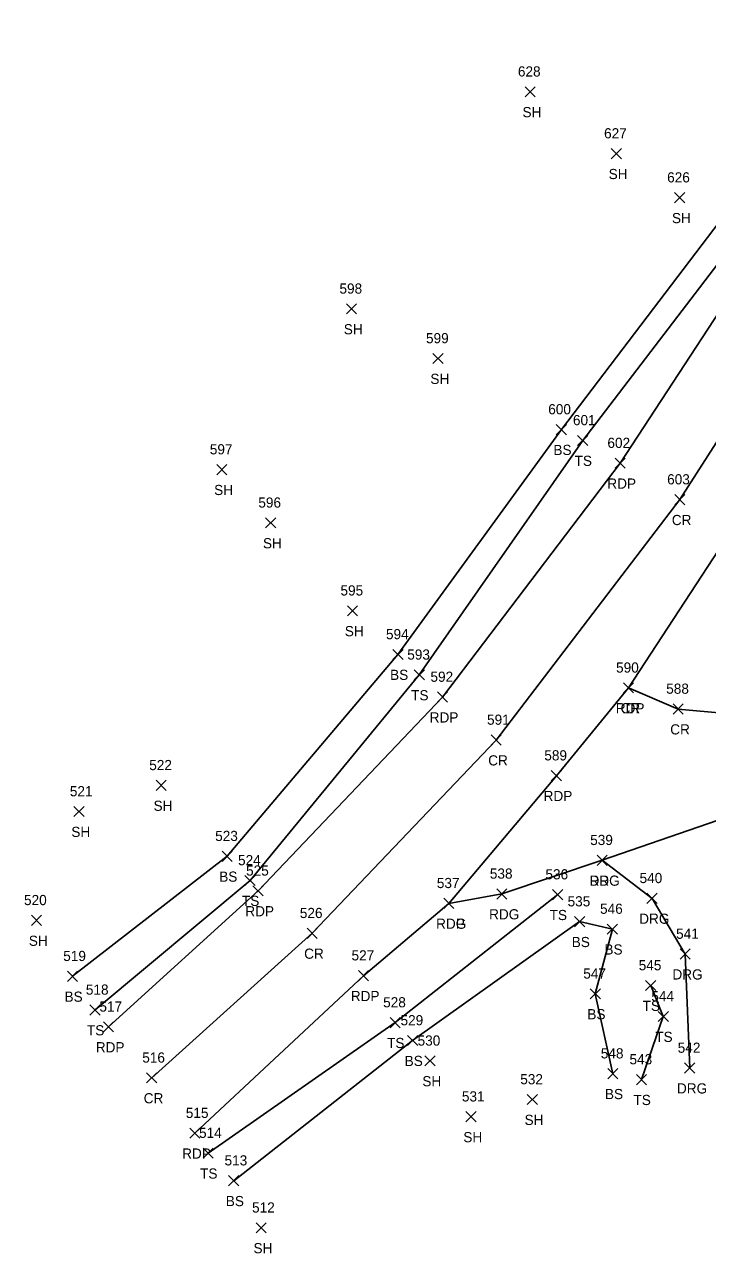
# Model space of a CAD drawing. Extents: x 1586965 to 1590952, y 716317 to 720029.
# Drawn here: x 1586964.8 to 1587099.1, y 719146.9 to 719388.4 of the extents above; entities that cross this region are included whole.
import ezdxf

# ---------------------------------------------------------------- set-up
doc = ezdxf.new("R2010")
doc.units = 0
for name, color, linetype in [('L_A', 7, 'Continuous'), ('L_I', 7, 'Continuous'), ('L_TIC', 7, 'Continuous'), ('LELB', 7, 'Continuous'), ('P_A', 7, 'Continuous'), ('P_I', 7, 'Continuous'), ('P_TIC', 7, 'Continuous'), ('PET', 7, 'Continuous'), ('PEU', 7, 'Continuous'), ('PRC', 7, 'Continuous'), ('R_A', 7, 'Continuous'), ('R_I', 7, 'Continuous'), ('R_TIC', 7, 'Continuous'), ('RDG', 7, 'Continuous')]:
    doc.layers.add(name, color=color, linetype=linetype)

msp = doc.modelspace()

# ---------------------------------------------------------------- linework, layer by layer
at = {"layer": 'L_TIC'}
for points in [[(1587063.22, 719374.22), (1587065.22, 719376.22)], [(1587065.22, 719374.22), (1587063.22, 719376.22)], [(1587080.16, 719362.06), (1587082.16, 719364.06)], [(1587082.16, 719362.06), (1587080.16, 719364.06)], [(1587092.61, 719353.4), (1587094.61, 719355.4)], [(1587094.61, 719353.4), (1587092.61, 719355.4)], [(1587028.08, 719331.55), (1587030.08, 719333.55)], [(1587030.08, 719331.55), (1587028.08, 719333.55)], [(1587045.11, 719321.8), (1587047.11, 719323.8)], [(1587047.11, 719321.8), (1587045.11, 719323.8)], [(1587069.35, 719307.83), (1587071.35, 719309.83)], [(1587071.35, 719307.83), (1587069.35, 719309.83)], [(1587073.55, 719305.69), (1587075.55, 719307.69)], [(1587075.55, 719305.69), (1587073.55, 719307.69)], [(1587002.59, 719299.96), (1587004.59, 719301.96)], [(1587004.59, 719299.96), (1587002.59, 719301.96)], [(1587012.19, 719289.49), (1587014.19, 719291.49)], [(1587014.19, 719289.49), (1587012.19, 719291.49)], [(1587028.28, 719272.22), (1587030.28, 719274.22)], [(1587030.28, 719272.22), (1587028.28, 719274.22)], [(1587037.23, 719263.63), (1587039.23, 719265.63)], [(1587039.23, 719263.63), (1587037.23, 719265.63)], [(1587041.41, 719259.62), (1587043.41, 719261.62)], [(1587043.41, 719259.62), (1587041.41, 719261.62)], [(1586990.68, 719237.9), (1586992.68, 719239.9)], [(1586992.68, 719237.9), (1586990.68, 719239.9)], [(1586974.51, 719232.76), (1586976.51, 719234.76)], [(1586976.51, 719232.76), (1586974.51, 719234.76)], [(1587003.64, 719223.97), (1587005.64, 719225.97)], [(1587005.64, 719223.97), (1587003.64, 719225.97)], [(1587008.14, 719219.21), (1587010.14, 719221.21)], [(1587010.14, 719219.21), (1587008.14, 719221.21)], [(1587068.64, 719216.43), (1587070.64, 719218.43)], [(1587070.64, 719216.43), (1587068.64, 719218.43)], [(1586966.15, 719211.37), (1586968.15, 719213.37)], [(1586968.15, 719211.37), (1586966.15, 719213.37)], [(1587072.95, 719211.12), (1587074.95, 719213.12)], [(1587074.95, 719211.12), (1587072.95, 719213.12)], [(1587079.38, 719209.66), (1587081.38, 719211.66)], [(1587081.38, 719209.66), (1587079.38, 719211.66)], [(1586973.22, 719200.38), (1586975.22, 719202.38)], [(1586975.22, 719200.38), (1586973.22, 719202.38)], [(1587086.92, 719198.57), (1587088.92, 719200.57)], [(1587088.92, 719198.57), (1587086.92, 719200.57)], [(1587076.02, 719196.93), (1587078.02, 719198.93)], [(1587078.02, 719196.93), (1587076.02, 719198.93)], [(1586977.66, 719193.77), (1586979.66, 719195.77)], [(1586979.66, 719193.77), (1586977.66, 719195.77)], [(1587036.67, 719191.28), (1587038.67, 719193.28)], [(1587038.67, 719191.28), (1587036.67, 719193.28)], [(1587089.4, 719192.48), (1587091.4, 719194.48)], [(1587091.4, 719192.48), (1587089.4, 719194.48)], [(1587040.1, 719187.75), (1587042.1, 719189.75)], [(1587042.1, 719187.75), (1587040.1, 719189.75)], [(1587043.54, 719183.76), (1587045.54, 719185.76)], [(1587045.54, 719183.76), (1587043.54, 719185.76)], [(1587079.48, 719181.24), (1587081.48, 719183.24)], [(1587081.48, 719181.24), (1587079.48, 719183.24)], [(1587085.12, 719180.08), (1587087.12, 719182.08)], [(1587087.12, 719180.08), (1587085.12, 719182.08)], [(1587063.63, 719176.16), (1587065.63, 719178.16)], [(1587065.63, 719176.16), (1587063.63, 719178.16)], [(1587051.59, 719172.78), (1587053.59, 719174.78)], [(1587053.59, 719172.78), (1587051.59, 719174.78)], [(1586999.91, 719165.62), (1587001.91, 719167.62)], [(1587001.91, 719165.62), (1586999.91, 719167.62)], [(1587004.93, 719160.21), (1587006.93, 719162.21)], [(1587006.93, 719160.21), (1587004.93, 719162.21)], [(1587010.33, 719150.95), (1587012.33, 719152.95)], [(1587012.33, 719150.95), (1587010.33, 719152.95)]]:
    msp.add_lwpolyline(points, dxfattribs=at)
at = {"layer": 'LELB'}
for points in [[(1586974.22, 719201.38), (1587004.64, 719224.97), (1587038.23, 719264.63), (1587070.35, 719308.83), (1587101.6, 719349.88), (1587119.36, 719390.75), (1587135.94, 719419.64), (1587149.18, 719457.32), (1587161.88, 719497.01), (1587171.82, 719537.32), (1587183.93, 719559.95), (1587196.31, 719595.67), (1587210.79, 719616.33), (1587226.54, 719644.19), (1587252.78, 719668.03), (1587275.41, 719699.75), (1587291.25, 719715.32), (1587307.92, 719729.13), (1587319.25, 719735.05), (1587320, 719753.34), (1587323.07, 719768.88), (1587320.57, 719781.92), (1587330.74, 719804.48), (1587340.87, 719823.38)], [(1586974.22, 719201.38), (1587004.64, 719224.97), (1587038.23, 719264.63), (1587070.35, 719308.83), (1587101.6, 719349.88), (1587119.36, 719390.75), (1587135.94, 719419.64), (1587149.18, 719457.32), (1587161.88, 719497.01), (1587171.82, 719537.32), (1587183.93, 719559.95), (1587196.31, 719595.67), (1587210.79, 719616.33), (1587226.54, 719644.19), (1587252.78, 719668.03), (1587275.41, 719699.75), (1587291.25, 719715.32), (1587307.92, 719729.13), (1587319.25, 719735.05), (1587320, 719753.34), (1587323.07, 719768.88), (1587320.57, 719781.92), (1587330.74, 719804.48), (1587340.87, 719823.38)], [(1586978.66, 719194.77), (1587009.14, 719220.21), (1587042.41, 719260.62), (1587074.55, 719306.69), (1587105.59, 719347.25), (1587126.81, 719387.29), (1587140.39, 719417.03), (1587155.04, 719455.09), (1587167.34, 719494.49), (1587179.82, 719533.81), (1587190.9, 719559.88), (1587204.29, 719592.61), (1587216.76, 719611.7), (1587236.63, 719636.62), (1587258.85, 719661.96), (1587283.81, 719691.81), (1587311.82, 719715.76), (1587323.53, 719725.34), (1587349.89, 719742.95), (1587377.37, 719757.84), (1587414.05, 719779.22)], [(1586978.66, 719194.77), (1587009.14, 719220.21), (1587042.41, 719260.62), (1587074.55, 719306.69), (1587105.59, 719347.25), (1587126.81, 719387.29), (1587140.39, 719417.03), (1587155.04, 719455.09), (1587167.34, 719494.49), (1587179.82, 719533.81), (1587190.9, 719559.88), (1587204.29, 719592.61), (1587216.76, 719611.7), (1587236.63, 719636.62), (1587258.85, 719661.96), (1587283.81, 719691.81), (1587311.82, 719715.76), (1587323.53, 719725.34), (1587349.89, 719742.95), (1587377.37, 719757.84), (1587414.05, 719779.22)], [(1587000.91, 719166.62), (1587037.67, 719192.28), (1587069.64, 719217.43)], [(1587000.91, 719166.62), (1587037.67, 719192.28), (1587069.64, 719217.43)], [(1587005.93, 719161.21), (1587041.1, 719188.75), (1587073.95, 719212.12), (1587080.38, 719210.66), (1587077.02, 719197.93), (1587080.48, 719182.24)], [(1587005.93, 719161.21), (1587041.1, 719188.75), (1587073.95, 719212.12), (1587080.38, 719210.66), (1587077.02, 719197.93), (1587080.48, 719182.24)], [(1587086.12, 719181.08), (1587090.4, 719193.48), (1587087.92, 719199.57)], [(1587086.12, 719181.08), (1587090.4, 719193.48), (1587087.92, 719199.57)]]:
    msp.add_lwpolyline(points, dxfattribs=at)
at = {"layer": 'P_TIC'}
for points in [[(1587080.9, 719301.22), (1587082.9, 719303.22)], [(1587082.9, 719301.22), (1587080.9, 719303.22)], [(1587092.64, 719294.06), (1587094.64, 719296.06)], [(1587094.64, 719294.06), (1587092.64, 719296.06)], [(1587082.56, 719257.07), (1587084.56, 719259.07)], [(1587084.56, 719257.07), (1587082.56, 719259.07)], [(1587082.56, 719257.07), (1587084.56, 719259.07)], [(1587084.56, 719257.07), (1587082.56, 719259.07)], [(1587045.97, 719255.26), (1587047.97, 719257.26)], [(1587047.97, 719255.26), (1587045.97, 719257.26)], [(1587092.33, 719252.91), (1587094.33, 719254.91)], [(1587094.33, 719252.91), (1587092.33, 719254.91)], [(1587056.54, 719246.82), (1587058.54, 719248.82)], [(1587058.54, 719246.82), (1587056.54, 719248.82)], [(1587068.37, 719239.81), (1587070.37, 719241.81)], [(1587070.37, 719239.81), (1587068.37, 719241.81)], [(1587077.39, 719223.18), (1587079.39, 719225.18)], [(1587079.39, 719223.18), (1587077.39, 719225.18)], [(1587009.72, 719217.17), (1587011.72, 719219.17)], [(1587011.72, 719217.17), (1587009.72, 719219.17)], [(1587057.65, 719216.57), (1587059.65, 719218.57)], [(1587059.65, 719216.57), (1587057.65, 719218.57)], [(1587047.24, 719214.72), (1587049.24, 719216.72)], [(1587049.24, 719214.72), (1587047.24, 719216.72)], [(1587047.24, 719214.72), (1587049.24, 719216.72)], [(1587049.24, 719214.72), (1587047.24, 719216.72)], [(1587020.35, 719208.83), (1587022.35, 719210.83)], [(1587022.35, 719208.83), (1587020.35, 719210.83)], [(1587030.46, 719200.5), (1587032.46, 719202.5)], [(1587032.46, 719200.5), (1587030.46, 719202.5)], [(1586980.32, 719190.44), (1586982.32, 719192.44)], [(1586982.32, 719190.44), (1586980.32, 719192.44)], [(1586988.8, 719180.42), (1586990.8, 719182.42)], [(1586990.8, 719180.42), (1586988.8, 719182.42)], [(1586997.3, 719169.55), (1586999.3, 719171.55)], [(1586999.3, 719169.55), (1586997.3, 719171.55)]]:
    msp.add_lwpolyline(points, dxfattribs=at)
at = {"layer": 'PET'}
for points in [[(1586981.32, 719191.44), (1587010.72, 719218.17), (1587046.97, 719256.26), (1587081.9, 719302.22), (1587109.59, 719344.47), (1587130.23, 719386.19), (1587143.83, 719415.56), (1587158.67, 719453.12), (1587172.27, 719492.43), (1587186.37, 719531.4), (1587196.72, 719557.08), (1587212.09, 719588.4), (1587223.39, 719607.14), (1587242.2, 719632.56), (1587263.71, 719657.85), (1587289.89, 719684.48), (1587313.81, 719705.37), (1587345, 719730.07), (1587380.68, 719751.95), (1587418.28, 719771.56)], [(1586998.3, 719170.55), (1587031.46, 719201.5), (1587048.24, 719215.72), (1587069.37, 719240.81), (1587083.56, 719258.07), (1587104.56, 719290.21), (1587133.86, 719331.71), (1587155.62, 719372.22), (1587169, 719404.76), (1587183.27, 719443.5), (1587197.56, 719483.83), (1587211.74, 719526.3), (1587221.19, 719546.28), (1587236.84, 719576.04), (1587246.13, 719590.54), (1587264.51, 719616.23), (1587283.97, 719638.96), (1587310.1, 719664.5), (1587332.49, 719682.99), (1587358.98, 719703.31), (1587395.82, 719726.18), (1587435.88, 719747.89)]]:
    msp.add_lwpolyline(points, dxfattribs=at)
at = {"layer": 'PEU'}
msp.add_lwpolyline([(1587048.24, 719215.72), (1587058.65, 719217.57), (1587078.39, 719224.18), (1587116.21, 719237.25), (1587149.4, 719248.8), (1587194.71, 719269.31)], dxfattribs=at)
at = {"layer": 'PRC'}
for points in [[(1586989.8, 719181.42), (1587021.35, 719209.83), (1587057.54, 719247.82), (1587093.64, 719295.06), (1587121.6, 719338.75), (1587145.01, 719385.55), (1587156.05, 719410.32), (1587170.73, 719448.3), (1587185.3, 719487.87), (1587199.88, 719528.69), (1587209.21, 719551.28), (1587224.26, 719582.11), (1587235.22, 719599.27), (1587253.6, 719624.57), (1587274.17, 719648.49), (1587299.95, 719674.27), (1587323.51, 719694.22), (1587352.02, 719715.49), (1587388.91, 719738.13), (1587428.57, 719759.37)], [(1586989.8, 719181.42), (1587021.35, 719209.83), (1587057.54, 719247.82), (1587093.64, 719295.06), (1587121.6, 719338.75), (1587145.01, 719385.55), (1587156.05, 719410.32), (1587170.73, 719448.3), (1587185.3, 719487.87), (1587199.88, 719528.69), (1587209.21, 719551.28), (1587224.26, 719582.11), (1587235.22, 719599.27), (1587253.6, 719624.57), (1587274.17, 719648.49), (1587299.95, 719674.27), (1587323.51, 719694.22), (1587352.02, 719715.49), (1587388.91, 719738.13), (1587428.57, 719759.37)], [(1587135.69, 719252.82), (1587111.5, 719252.24), (1587093.33, 719253.91), (1587083.56, 719258.07)], [(1587135.69, 719252.82), (1587111.5, 719252.24), (1587093.33, 719253.91), (1587083.56, 719258.07)]]:
    msp.add_lwpolyline(points, dxfattribs=at)
at = {"layer": 'R_TIC'}
for points in [[(1587077.39, 719223.18), (1587079.39, 719225.18)], [(1587079.39, 719223.18), (1587077.39, 719225.18)], [(1587087.18, 719215.7), (1587089.18, 719217.7)], [(1587089.18, 719215.7), (1587087.18, 719217.7)], [(1587093.7, 719204.75), (1587095.7, 719206.75)], [(1587095.7, 719204.75), (1587093.7, 719206.75)], [(1587094.59, 719182.35), (1587096.59, 719184.35)], [(1587096.59, 719182.35), (1587094.59, 719184.35)]]:
    msp.add_lwpolyline(points, dxfattribs=at)
at = {"layer": 'RDG'}
msp.add_lwpolyline([(1587078.39, 719224.18), (1587088.18, 719216.7), (1587094.7, 719205.75), (1587095.59, 719183.35)], dxfattribs=at)

# ---------------------------------------------------------------- texts
at = {"layer": 'L_A'}
for s, p in [('SH', (1587062.71, 719370.22)), ('SH', (1587079.65, 719358.06)), ('SH', (1587092.1, 719349.4)), ('SH', (1587027.57, 719327.55)), ('SH', (1587044.6, 719317.8)), ('BS', (1587068.79, 719303.83)), ('TS', (1587072.96, 719301.69)), ('SH', (1587002.08, 719295.96)), ('SH', (1587011.68, 719285.49)), ('SH', (1587027.77, 719268.22)), ('BS', (1587036.68, 719259.63)), ('TS', (1587040.82, 719255.62)), ('SH', (1586990.17, 719233.9)), ('SH', (1586974, 719228.76)), ('BS', (1587003.08, 719219.97)), ('TS', (1587007.55, 719215.21)), ('TS', (1587068.05, 719212.43)), ('SH', (1586965.64, 719207.37)), ('BS', (1587072.39, 719207.12)), ('BS', (1587078.82, 719205.66)), ('BS', (1586972.66, 719196.38)), ('TS', (1587086.33, 719194.57)), ('BS', (1587075.46, 719192.93)), ('TS', (1586977.07, 719189.77)), ('TS', (1587036.08, 719187.28)), ('TS', (1587088.81, 719188.48)), ('BS', (1587039.54, 719183.75)), ('SH', (1587043.02, 719179.76)), ('BS', (1587078.92, 719177.24)), ('TS', (1587084.53, 719176.08)), ('SH', (1587063.12, 719172.16)), ('SH', (1587051.08, 719168.78)), ('TS', (1586999.32, 719161.62)), ('BS', (1587004.37, 719156.21)), ('SH', (1587009.82, 719146.95))]:
    msp.add_text(s, height=2, dxfattribs=at).set_placement(p)
at = {"layer": 'L_I'}
for s, p in [('628', (1587061.81, 719378.22)), ('627', (1587078.75, 719366.06)), ('626', (1587091.15, 719357.4)), ('598', (1587026.72, 719335.55)), ('599', (1587043.74, 719325.8)), ('600', (1587067.77, 719311.83)), ('601', (1587072.63, 719309.69)), ('597', (1587001.23, 719303.96)), ('596', (1587010.77, 719293.49)), ('595', (1587026.92, 719276.22)), ('594', (1587035.87, 719267.63)), ('593', (1587040.05, 719263.62)), ('522', (1586989.32, 719241.9)), ('521', (1586973.71, 719236.76)), ('523', (1587002.28, 719227.97)), ('524', (1587006.78, 719223.21)), ('536', (1587067.22, 719220.43)), ('520', (1586964.7, 719215.37)), ('535', (1587071.58, 719215.12)), ('546', (1587077.96, 719213.66)), ('519', (1586972.41, 719204.38)), ('547', (1587074.66, 719200.93)), ('545', (1587085.56, 719202.57)), ('518', (1586976.86, 719197.77)), ('544', (1587088.04, 719196.48)), ('528', (1587035.31, 719195.28)), ('529', (1587038.73, 719191.75)), ('530', (1587042.09, 719187.76)), ('548', (1587078.11, 719185.24)), ('543', (1587083.75, 719184.08)), ('532', (1587062.27, 719180.16)), ('531', (1587050.8, 719176.78)), ('514', (1586999.11, 719169.62)), ('513', (1587004.13, 719164.21)), ('512', (1587009.54, 719154.95))]:
    msp.add_text(s, height=2, dxfattribs=at).set_placement(p)
at = {"layer": 'P_A'}
for s, p in [('RDP', (1587079.39, 719297.22)), ('CR', (1587092.07, 719290.06)), ('RDP', (1587081.05, 719253.07)), ('CR', (1587081.99, 719253.07)), ('RDP', (1587044.46, 719251.26)), ('CR', (1587091.76, 719248.91)), ('CR', (1587055.97, 719242.82)), ('RDP', (1587066.86, 719235.81)), ('RDG', (1587075.88, 719219.18)), ('RDP', (1587008.21, 719213.17)), ('RDG', (1587045.72, 719210.72)), ('RDP', (1587045.72, 719210.72)), ('RDG', (1587056.14, 719212.57)), ('CR', (1587019.78, 719204.83)), ('RDP', (1587028.95, 719196.5)), ('RDP', (1586978.81, 719186.44)), ('CR', (1586988.23, 719176.42)), ('RDP', (1586995.79, 719165.55))]:
    msp.add_text(s, height=2, dxfattribs=at).set_placement(p)
at = {"layer": 'P_I'}
for s, p in [('602', (1587079.41, 719305.22)), ('603', (1587091.15, 719298.06)), ('590', (1587081.11, 719261.07)), ('590', (1587081.11, 719261.07)), ('592', (1587044.61, 719259.26)), ('588', (1587090.97, 719256.91)), ('591', (1587055.74, 719250.82)), ('589', (1587067, 719243.81)), ('539', (1587076.02, 719227.18)), ('525', (1587008.36, 719221.17)), ('538', (1587056.29, 719220.57)), ('537', (1587045.87, 719218.72)), ('537', (1587045.87, 719218.72)), ('526', (1587018.93, 719212.83)), ('527', (1587029.1, 719204.5)), ('517', (1586979.52, 719194.44)), ('516', (1586987.95, 719184.42)), ('515', (1586996.51, 719173.55))]:
    msp.add_text(s, height=2, dxfattribs=at).set_placement(p)
at = {"layer": 'R_A'}
for p in [(1587075.88, 719219.18), (1587085.66, 719211.7), (1587092.19, 719200.75), (1587093.08, 719178.35)]:
    msp.add_text('DRG', height=2, dxfattribs=at).set_placement(p)
at = {"layer": 'R_I'}
for s, p in [('539', (1587076.02, 719227.18)), ('540', (1587085.73, 719219.7)), ('541', (1587092.91, 719208.75)), ('542', (1587093.23, 719186.35))]:
    msp.add_text(s, height=2, dxfattribs=at).set_placement(p)

doc.saveas('drawing.dxf')
